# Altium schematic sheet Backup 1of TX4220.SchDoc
size A4; SheetNumber: 0; SheetTotal: 0
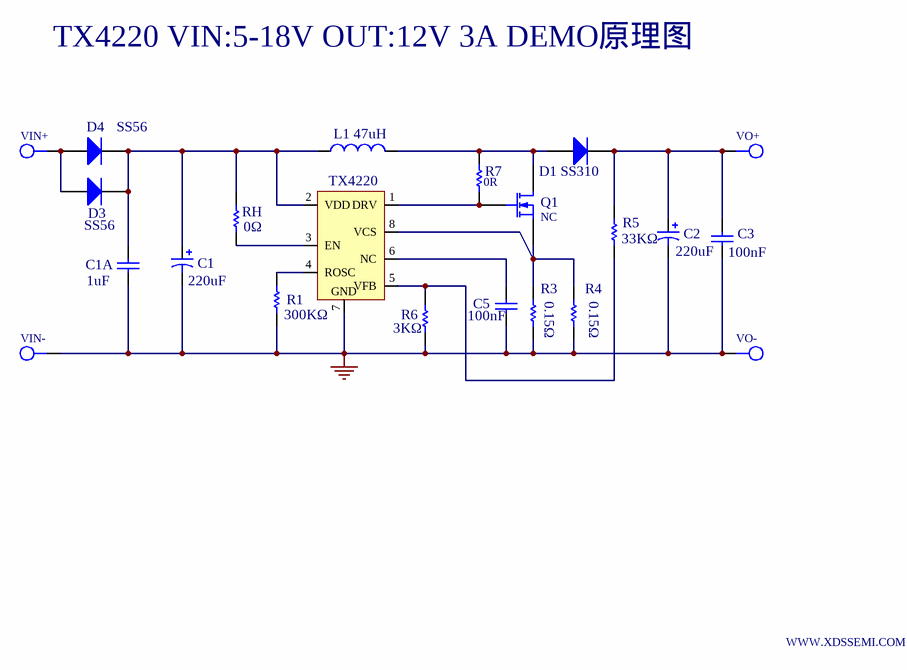
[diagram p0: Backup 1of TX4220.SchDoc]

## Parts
C1  (no value)  [C8*12]
C1A  (no value)  [r0805]
C2  (no value)  [C10*16]
C3  (no value)  [r1206]
C5  (no value)  [r0805]
D1_SS310  (no value)  [SMB]
D3  SS56  [SMB]  (value not drawn)
D4  SS56  [SMB]  (value not drawn)
L1_47uH  (no value)  [cdrh127]
Q1  NC  [to252]
R1  (no value)  [r0805]
R3  (no value)  [r1206]
R4  (no value)  [r1206]
R5  (no value)  [r0805]
R6  (no value)  [r0805]
R7  0R  [r0805]
RH  (no value)  [r0805]
TX4220  (no value)
VIN+  *  [P]  (value not drawn)
VIN-  *  [P]  (value not drawn)
VO+  (no value)  [P]
VO-  *  [P]  (value not drawn)

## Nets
GND: C1.2 C1A.1 C2.2 C3.1 C5.1 R1.1 R3.2 R4.2 R6.2 TX4220.7 VIN-.P VO-.P
NetC1_1: C1.1 C1A.2 D3.2(K) D4.2(K) L1_47uH.1 RH.2 TX4220.2(VDD)
NetC2_1: C2.1 C3.2 D1_SS310.2(K) R5.1 VO+.P
NetC5_2: C5.2 TX4220.6(NC)
NetD1_SS310_1: D1_SS310.1(A) L1_47uH.2 Q1.2(D) R7.2
NetD3_1: D3.1(A) D4.1(A) VIN+.P
NetQ1_1: Q1.1(G) R7.1 TX4220.1(DRV)
NetQ1_3: Q1.3(S) R3.1 R4.1 TX4220.8(VCS)
NetR1_2: R1.2 TX4220.4(ROSC)
NetR5_2: R5.2 R6.1 TX4220.5(VFB)
NetRH_1: RH.1 TX4220.3(EN)

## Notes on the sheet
- TX4220 VIN:5-18V OUT:12V 3A DEMO原理图
- (near D4) SS56
- SS56
- (near RH) 0Ω
- (near R5) 33KΩ
- (near C1A) 1uF
- (near C1) 220uF
- (near R3) 0.15Ω
- (near R4) 0.15Ω
- 220uF
- (near C3) 100nF
- 300KΩ
- (near R6) 3KΩ
- (near C5) 100nF
- WWW.XDSSEMI.COM

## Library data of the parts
C1 C2 = Cap Pol1: Polarized Capacitor (Radial)
C1A C3 C5 = Cap: Capacitor
D1_SS310 D3 D4 = Diode: Default Diode
L1_47uH = Inductor: Code_IEC: 1005
Q1 = MOSFET-N: N-Channel MOSFET
R1 R3-R7 RH = Res1: Resistor
TX4220 = Component_1
VIN+ VIN- VO+ VO- = P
